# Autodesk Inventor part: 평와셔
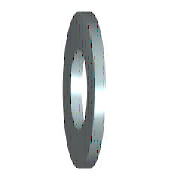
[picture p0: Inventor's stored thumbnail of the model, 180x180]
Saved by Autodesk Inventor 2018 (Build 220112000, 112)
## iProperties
IsCustomPart: 1
Created: 2012-02
Part Number: 평와셔
Material: 강철, 연강
Description: 평면 와셔 - 초대형 시리즈 - 제품 등급 C
Document SubType Name: Modeling
Standard: ISO 7094
Designer: mduedu
Standard Revision: Second edition 2000-06-01
Standards Organization: ISO
Language: ko-KR
Size Designation: ST 5 - 100 HV
Categories: <MemberInstance><Categories><Category DisplayName="조임쇠" InternalName="e4da775c-781d-43d5-af7c-5136215cf5a6" Mnemonic="FSTN"><Category DisplayName="와셔" InternalN
Density: 7.86 g/cm^3
Mass: 3.62677 g
Surface Area: 6.09076 cm^2
Volume: 0.461421 cm^3
Appearance: 강철
Author: mduedu
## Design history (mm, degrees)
sketch "스케치"
  geometry: C1 r 9 at (0, 0); C2 r 2.75 at (0, 0); 1 further point
  constraints: 2 centre point, 2 coincident
  dimensions: "d0" = 5.5 diameter of C2 (= SD1); "d1" = 18 diameter of C1 (= SD2)
extrude "본체" new body sketch "스케치" distance "d2" = 2 (= SD); taper "d3" = 0 deg
workaxis "Work Axis1"
workplane "Work Plane1"
body "Solid1"
other parameters: "SD1" = 5.5 [user parameter; used in 1 equation term], "SD2" = 18 [user parameter; used in 1 equation term], "SD" = 2 [user parameter; used in 1 equation term], "d4" = 0, "d5" = 0, "d6" = 0, "d7" = 0, "NND" = 5 [user parameter]
